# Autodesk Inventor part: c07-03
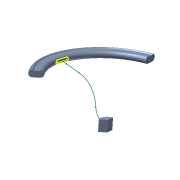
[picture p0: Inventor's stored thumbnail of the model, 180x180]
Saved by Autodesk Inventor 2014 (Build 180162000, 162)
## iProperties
Created: 2010-12
Part Number: c07-03
Document SubType Name: Modeling
Designer: Thom Tremblay
Density: 1 g/cm^3
Material: Generic
Appearance: Light Steel Blue
Author: Thom Tremblay
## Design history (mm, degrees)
sketch "Sketch2"
  geometry: L1 (0, 0)-(-11.43, 0); L2 (-11.43, 0)-(-11.43, 16.51); L3 (-11.43, 16.51)-(0, 16.51); L4 (0, 16.51)-(0, 0); L5 (-96.52, 66.04)-(-86.36, 66.04); L6 (-86.36, 76.2)-(-96.52, 76.2); L7 (-95.25, 74.93)-(-87.63, 74.93); L8 (-96.52, 76.2)-(-95.25, 74.93); L9 (-86.36, 76.2)-(-87.63, 74.93); A1 r 5.08 centre (-86.36, 71.12) between (-86.36, 66.04) and (-86.36, 76.2); A2 r 5.08 centre (-96.52, 71.12) between (-96.52, 76.2) and (-96.52, 66.04)
  constraints: 18 end point, 4 parallel, 4 point on circle, 4 tangent, 2 centre point, 2 horizontal, 2 perpendicular
  dimensions: "d6" = 16.51 distance of L1.end L2.end; "d7" = 22.86 diameter of L2 L4; "d10" = 5.08 radius of A1; "d11" = 20.32 dimension on A2 A1; "d12" = 3.81 distance from line of A1.centre L7; "d13" = 7.62 distance of L7.start L7.end; "d14" = 76.2 distance from line of L6.end L1; "d15" = 203.2 dimension on A2 L4
revolve "Revolution1" sketch "Sketch2" stored, may be unused: angle "d16" = 120 deg
sketch "Plane Sketch 1"
  geometry: L1 (-48.26, -83.589)-(-43.18, -74.79) reference; L2 (-48.26, 83.589)-(-43.18, 74.79) reference; L3 (0, 0)-(-85.598, 31.155); L4 (0, 0)-(-86.36, 0); A1 r 86.36 centre (0, 0) between (-43.18, 74.79) and (-43.18, -74.79) reference; A2 r 96.52 centre (0, 0) between (-48.26, 83.589) and (-48.26, -83.589) reference; 1 further point
  constraints: 4 end point, 1 point on circle
  dimensions: "d65" = 20 deg angle of L3 L4; "d66" = 91.09202 distance of L3.start L3.end
workplane "Work Plane2"
sketch "Sketch10"
  geometry: L1 (-8.89, 5.08)-(8.89, 5.08); L2 (-8.89, 2.54)-(8.89, 2.54); L3 (8.89, 7.62)-(-8.89, 7.62); A1 r 2.54 centre (-8.89, 5.08) between (-8.89, 7.62) and (-8.89, 2.54); A2 r 2.54 centre (8.89, 5.08) between (8.89, 2.54) and (8.89, 7.62); 2 further points
  constraints: 8 end point, 4 point on circle, 4 tangent, 2 centre point, 1 midpoint, 1 parallel, 1 vertical alignment
  dimensions: "d67" = 71.12 distance from line of L1 point (0, -66.04); "d68" = 17.78 distance of L3.start L3.end; "d69" = 2.54 radius of A2
sketch "Loft Sketch 1"
  node "Project from Sketch10"
sketch "Sketch 2"
  geometry: C1 r 3.81 at (0, 7.62); 1 further point
  constraints: 1 centre point, 1 vertical alignment
  dimensions: "d63" = 7.62 diameter of C1; "d64" = 7.62 distance of point (0, 0) C1.centre
sketch "Loft Sketch 2"
  node "Project from Sketch 2"
sketch "Rail Sketch 1"
  geometry: L1 (11.43, 0)-(-6.921, 0); L2 (76.378, 27.799)-(69.218, 25.193); L3 (0, 0)-(5.715, -9.899) reference; L4 (5.715, 9.899)-(0, 0) reference; A1 r 50.8 centre (86.592, -22.543) between (69.218, 25.193) and (53.126, 15.675); A2 r 63.293 centre (11.43, 63.293) between (11.43, 0) and (53.126, 15.675); A3 r 11.43 centre (0, 0) between (5.715, -9.899) and (5.715, 9.899) reference
  constraints: 4 end point, 4 point on circle, 3 tangent, 2 centre point, 1 horizontal
  dimensions: "d73" = 50.8 radius of A1; "d75" = 7.62 distance of L2.start L2.end; "d76" = 20 deg angle of L2 L1 (= d65)
sketch "Rail Sketch 2"
  geometry: L1 (-76.378, 71.12)-(-95.236, 71.12); L2 (-76.378, 71.12)-(-69.018, 69.148); L3 (-11.43, 7.62)-(5.882, 7.62); L4 (-11.43, 16.51)-(-11.43, 0) reference; A1 r 17.78 centre (-11.43, 25.4) between (-29.076, 23.224) and (-11.43, 7.62); A2 r 54.441 centre (-83.108, 16.562) between (-29.076, 23.224) and (-69.018, 69.148); 1 further point
  constraints: 6 end point, 4 point on circle, 3 tangent, 2 centre point, 1 horizontal, 1 perpendicular
  dimensions: "d78" = 15 deg angle of L2 L1; "d79" = 7.62 distance of L1.start L2.end; "d80" = 17.78 radius of A1
sketch "3D Sketch4"
  node "3D Intersection2"
body "Solid1"
